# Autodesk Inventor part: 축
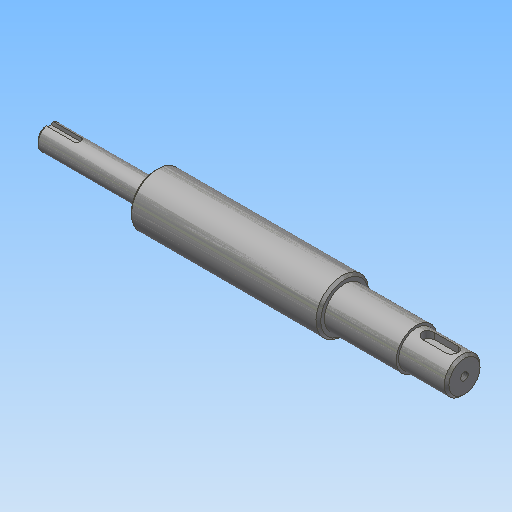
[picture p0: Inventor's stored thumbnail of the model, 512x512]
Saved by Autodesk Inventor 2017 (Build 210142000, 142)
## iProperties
Created: 2016-05
Part Number: 축
Document SubType Name: Modeling
Designer: mduedu
Density: 7.86 g/cm^3
Material: 강철, 연강
Appearance: 강철
Author: mduedu
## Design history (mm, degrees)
sketch "스케치1"
  geometry: L1 (-42, 11)-(-42, 5); L2 (37, 11)-(37, 8.5); L3 (-87, 0)-(87, 0); L4 (-42, 11)-(37, 11); L5 (37, 11)-(37, 8.5); L6 (-42, 11)-(-42, 5); L7 (-42, 5)-(-87, 5); L8 (-87, 5)-(-87, 0); L9 (37, 8.5)-(67, 8.5); L10 (87, 7.5)-(87, 0); L11 (67, 8.5)-(67, 7.5); L12 (67, 7.5)-(87, 7.5); 1 further point
  constraints: 24 end point, 9 perpendicular, 2 midpoint, 1 horizontal
  dimensions: "d0" = 22 diameter of L4 L3; "d1" = 10 diameter of L7 L3; "d2" = 45 distance between parallel lines of L8 L1; "d3" = 50 distance between parallel lines of L10 L2; "d4" = 15 diameter of L12 L3; "d5" = 20 distance between parallel lines of L10 L11; "d29" = 79 distance of L1.start L2.start; "d37" = 17 diameter of L9 L3
revolve "회전1" stored, may be unused: angle "d6" = 90 deg
chamfer "모따기2" distance "d32" = 1; stored, may be unused: second distance "d33" = 2, angle "d34" = 45 deg
node "작업 평면4"
sketch "스케치4"
  geometry: L1 (-5, 2.5)-(5, 2.5); L2 (5, -2.5)-(-5, -2.5); L3 (-10, -6.5)-(-10, 6.5) reference; A1 r 2.5 centre (5, 0) between (5, -2.5) and (5, 2.5); A2 r 2.5 centre (-5, 0) between (-5, 2.5) and (-5, -2.5); 1 further point
  constraints: 4 end point, 4 point on circle, 4 tangent, 2 centre point, 1 horizontal, 1 horizontal alignment, 1 parallel
  dimensions: "d20" = 5 distance between parallel lines of L2 L1; "d21" = 15 dimension on A1 A2; "d35" = 2.5 distance edge to line of A2 L3
extrude "돌출3" cut sketch "스케치4" distance "d23" = 3; taper "d24" = 0 deg
node "작업 평면5"
sketch "스케치5"
  geometry: L1 (22.5, 1.5)-(10, 1.5); L2 (10, -1.5)-(22.5, -1.5); L3 (22.5, 4)-(22.5, -4) reference; A1 r 1.5 centre (10, 0) between (10, 1.5) and (10, -1.5); 3 further points
  constraints: 4 end point, 2 horizontal alignment, 2 point on circle, 2 point on line, 2 tangent, 1 centre point, 1 coincident, 1 horizontal, 1 midpoint
  dimensions: "d25" = 3 distance between parallel lines of L2 L1; "d36" = 14 dimension on A1 L3
extrude "돌출4" cut sketch "스케치5" distance "d27" = 1.8; taper "d28" = 0 deg
hole "구멍1" diameter "d40" = 3.242; stored, may be unused: countersink angle "d44" = 90 deg, drill point angle "d46" = 118 deg; dims "d41" = 10, "d42" = 4, "d43" = 2, "d45" = 12, "d47" = 10, "d48" = 10
node "솔리드1"
